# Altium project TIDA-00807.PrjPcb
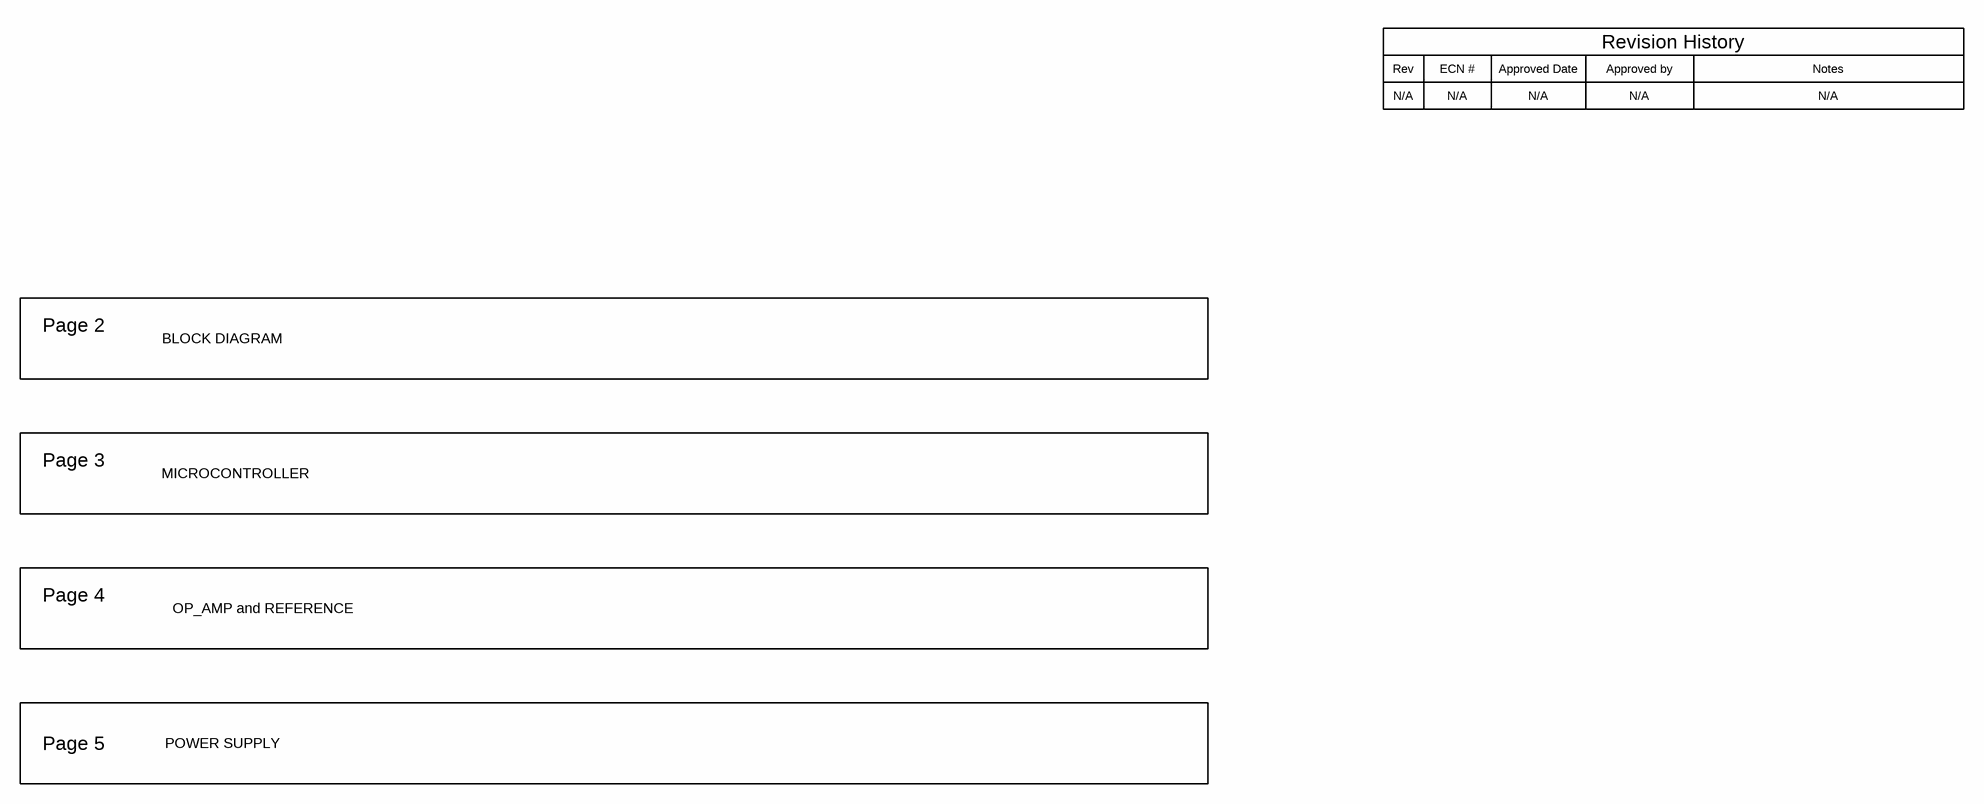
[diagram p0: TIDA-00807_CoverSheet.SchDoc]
CopyrightYear: 2016; PCB_Layout: Manjunath M; PCB_Rev: E2; PRJ_Customer: Public Release; PRJ_Engineer: Srinivasa; PRJ_Number: TIDA-00807; PRJ_Title: TIDA-00807; SCH_Rev: E2; TechSupport: http://www.ti.com/support; TID: N/A
6 sheets, 166 parts. Net scope: flat (ports and power ports of the same name join across sheets).
Board file: TIDA-00807_E2.PcbDoc
Sheets:
  TIDA-00807_CoverSheet.SchDoc
  TIDA-00807_BLOCKDIAGRAM.SchDoc
  TIDA-00807_MICROCONTROLLER.SchDoc
  TIDA-00807_OP_AMP and REFERENCE.SchDoc
  TIDA-00807_POWER SUPPLY.SchDoc
  TIDA-00807_EVM_Hardware.SchDoc

## Sheet TIDA-00807_CoverSheet.SchDoc: CoverSheet
size 431 x 279 mm; Date: Not shown in title block; ApprovedBy: Not shown in title block; CheckedBy: Not shown in title block; Author: Not shown in title block; CompanyName: Not shown in title block; DrawnBy: Srinivasa; Engineer: Srinivasa; Organization: Not shown in title block; Address1: Not shown in title block; Address2: Not shown in title block; Address3: Not shown in title block; Address4: Not shown in title block; DocumentNumber: 1; Revision: Use project parameter SCH_Rev; SheetNumber: 1; SheetTotal: 6; PageSetup: Record=PageOptions¦CenterHorizontal=True¦CenterVertical=True¦PrintScale=1.00¦XCorrection=1.00¦YCorrection=1.00¦PrintKind=0¦BorderSize=5000000¦LeftOffset=0¦BottomOffset=0¦Orientation=2¦PaperLength=1000¦PaperWidth=1000¦Scale=100¦PaperSource=15¦PrintQuality=600¦MediaType=1¦DitherType=10¦PaperKind=Letter¦PrintScaleMode=1

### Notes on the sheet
- Rev
- N/A
- ECN #
- Approved Date
- Approved by
- Revision History
- Notes
- Page 2
- BLOCK DIAGRAM
- Page 3
- MICROCONTROLLER
- Page 4
- OP_AMP and REFERENCE
- Page 5
- POWER SUPPLY

## Sheet TIDA-00807_BLOCKDIAGRAM.SchDoc: BLOCK DIAGRAM
size 431 x 279 mm; Date: Not shown in title block; ApprovedBy: Not shown in title block; CheckedBy: Not shown in title block; Author: Not shown in title block; CompanyName: Not shown in title block; DrawnBy: Srinivasa; Engineer: Srinivasa; Organization: Not shown in title block; Address1: Not shown in title block; Address2: Not shown in title block; Address3: Not shown in title block; Address4: Not shown in title block; DocumentNumber: 1; Revision: Use project parameter SCH_Rev; SheetNumber: 2; SheetTotal: 6; PageSetup: Record=PageOptions¦CenterHorizontal=True¦CenterVertical=True¦PrintScale=1.00¦XCorrection=1.00¦YCorrection=1.00¦PrintKind=0¦BorderSize=5000000¦LeftOffset=0¦BottomOffset=0¦Orientation=2¦PaperLength=1000¦PaperWidth=1000¦Scale=100¦PaperSource=15¦PrintQuality=600¦MediaType=1¦DitherType=10¦PaperKind=Letter¦PrintScaleMode=1
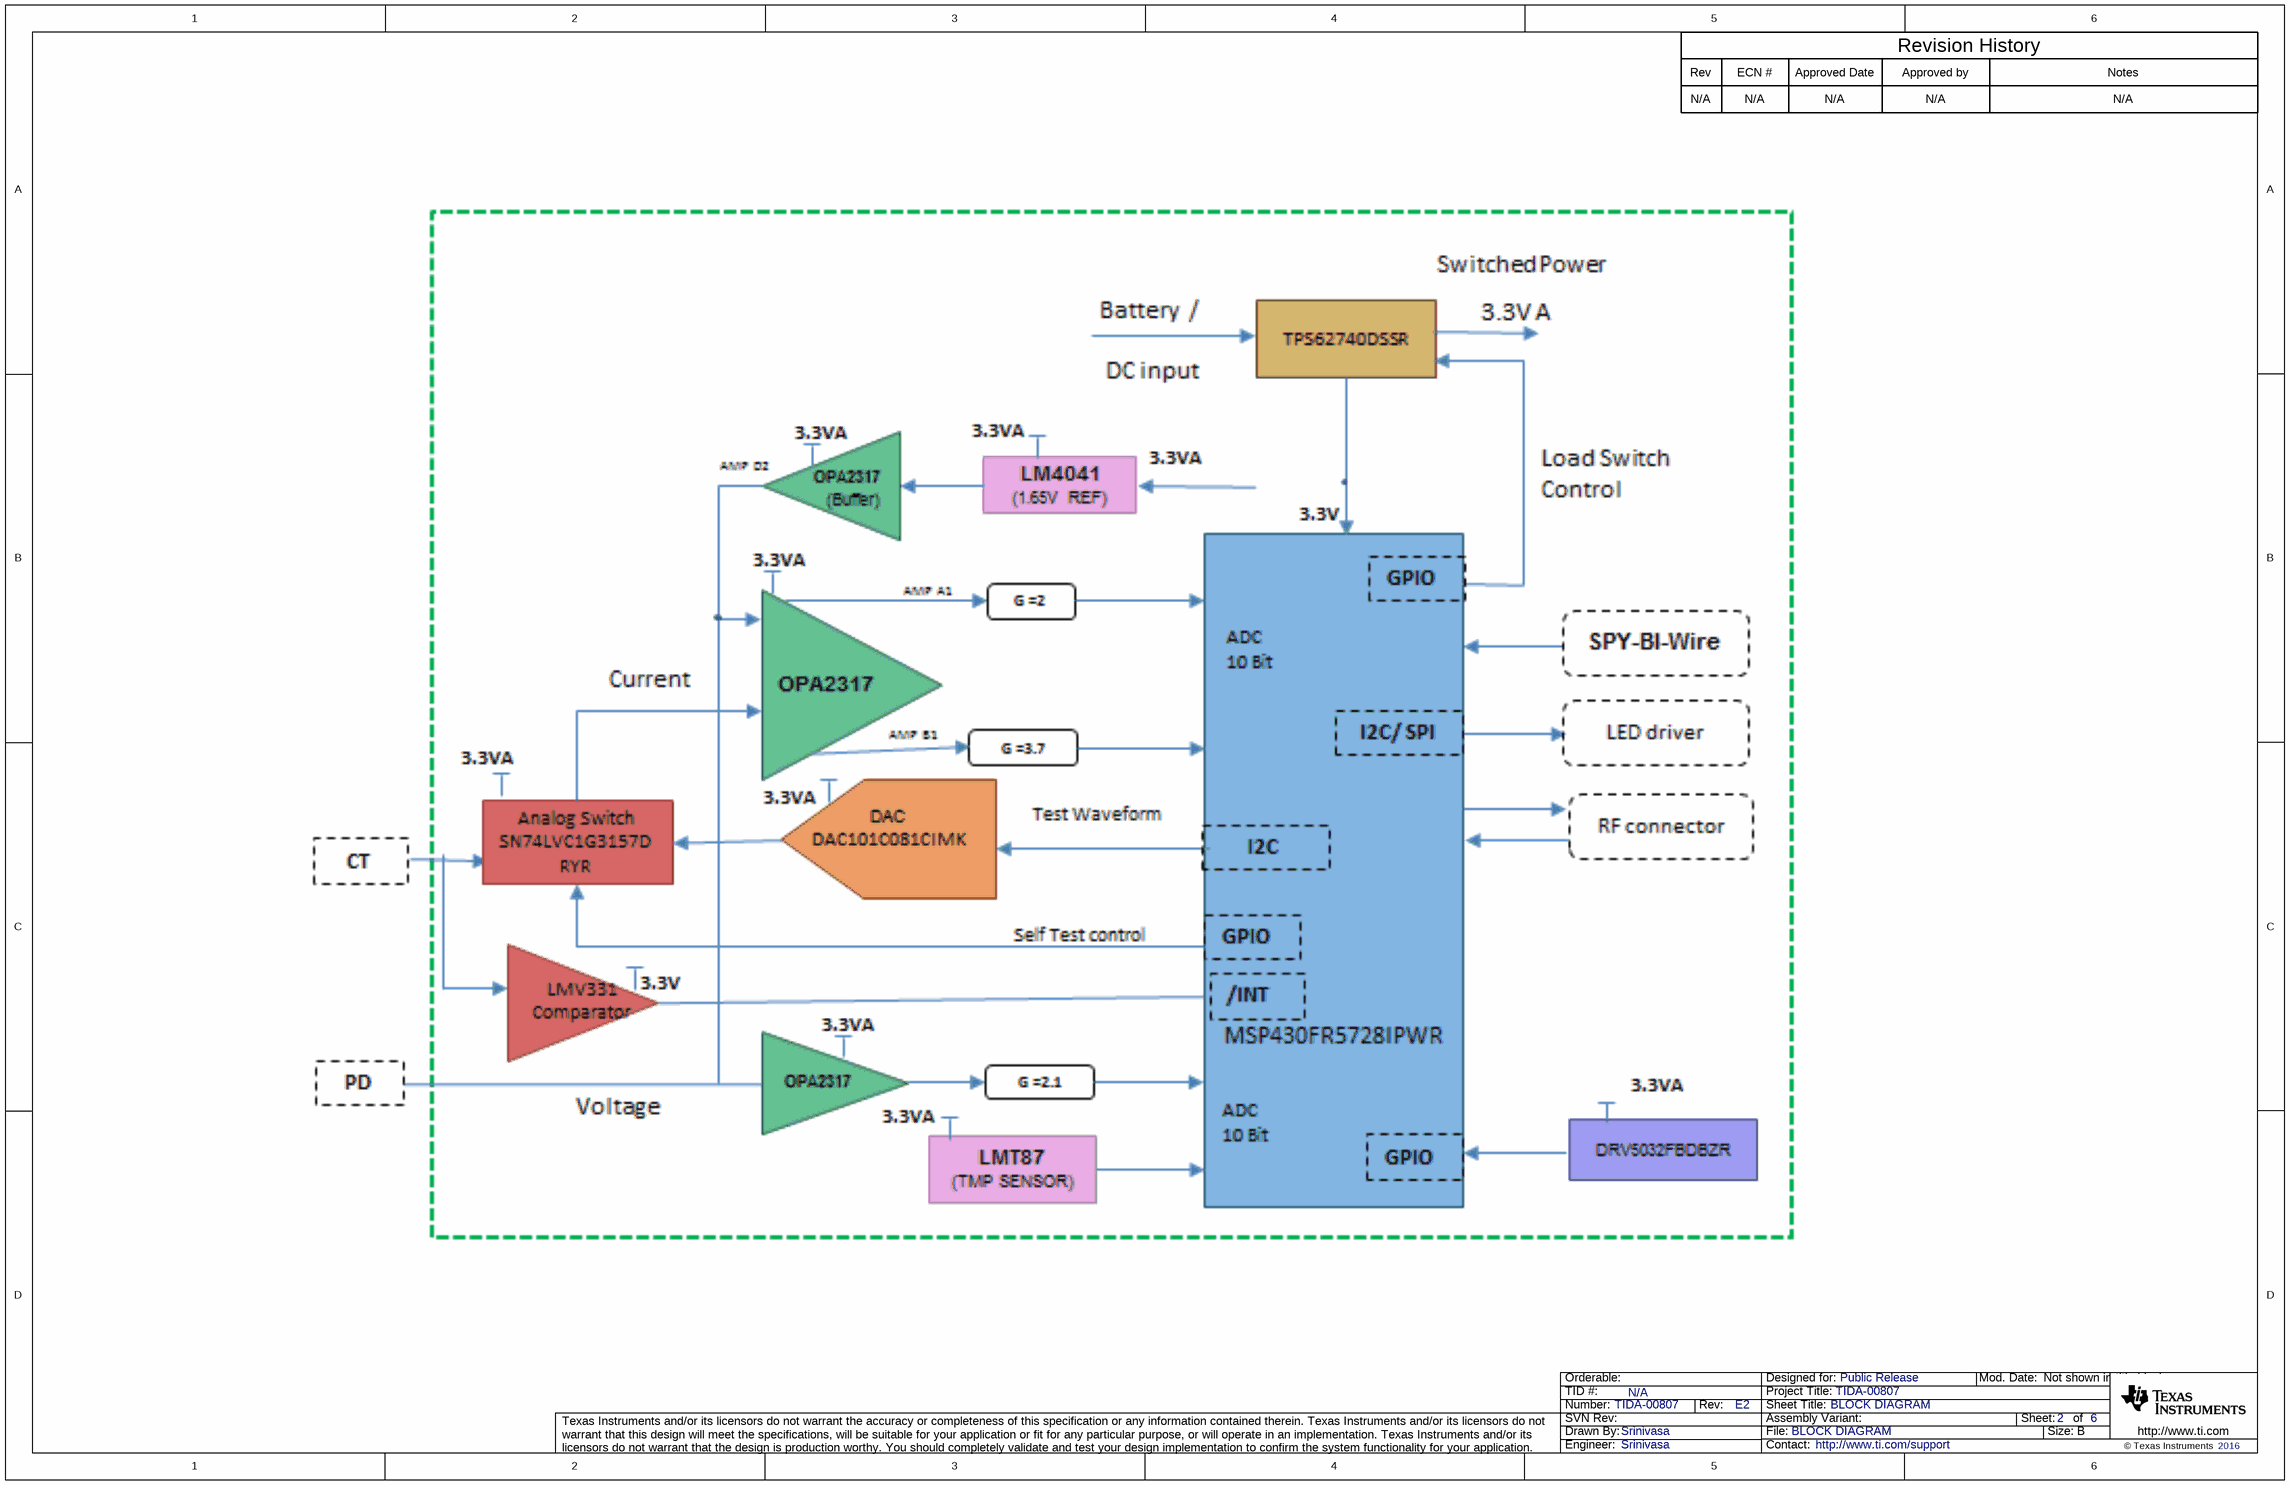
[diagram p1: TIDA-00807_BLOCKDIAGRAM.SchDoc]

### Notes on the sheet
- Rev
- N/A
- ECN #
- Approved Date
- Approved by
- Revision History
- Notes

## Sheet TIDA-00807_MICROCONTROLLER.SchDoc: MICROCONTROLLER
size 431 x 279 mm; Date: Not shown in title block; ApprovedBy: Not shown in title block; CheckedBy: Not shown in title block; Author: Not shown in title block; CompanyName: Not shown in title block; DrawnBy: Srinivasa; Engineer: Srinivasa; Organization: Not shown in title block; Address1: Not shown in title block; Address2: Not shown in title block; Address3: Not shown in title block; Address4: Not shown in title block; DocumentNumber: 1; Revision: Use project parameter SCH_Rev; SheetNumber: 3; SheetTotal: 6; PageSetup: Record=PageOptions¦CenterHorizontal=True¦CenterVertical=True¦PrintScale=1.00¦XCorrection=1.00¦YCorrection=1.00¦PrintKind=0¦BorderSize=5000000¦LeftOffset=0¦BottomOffset=0¦Orientation=2¦PaperLength=1000¦PaperWidth=1000¦Scale=100¦PaperSource=15¦PrintQuality=600¦MediaType=1¦DitherType=10¦PaperKind=Letter¦PrintScaleMode=1
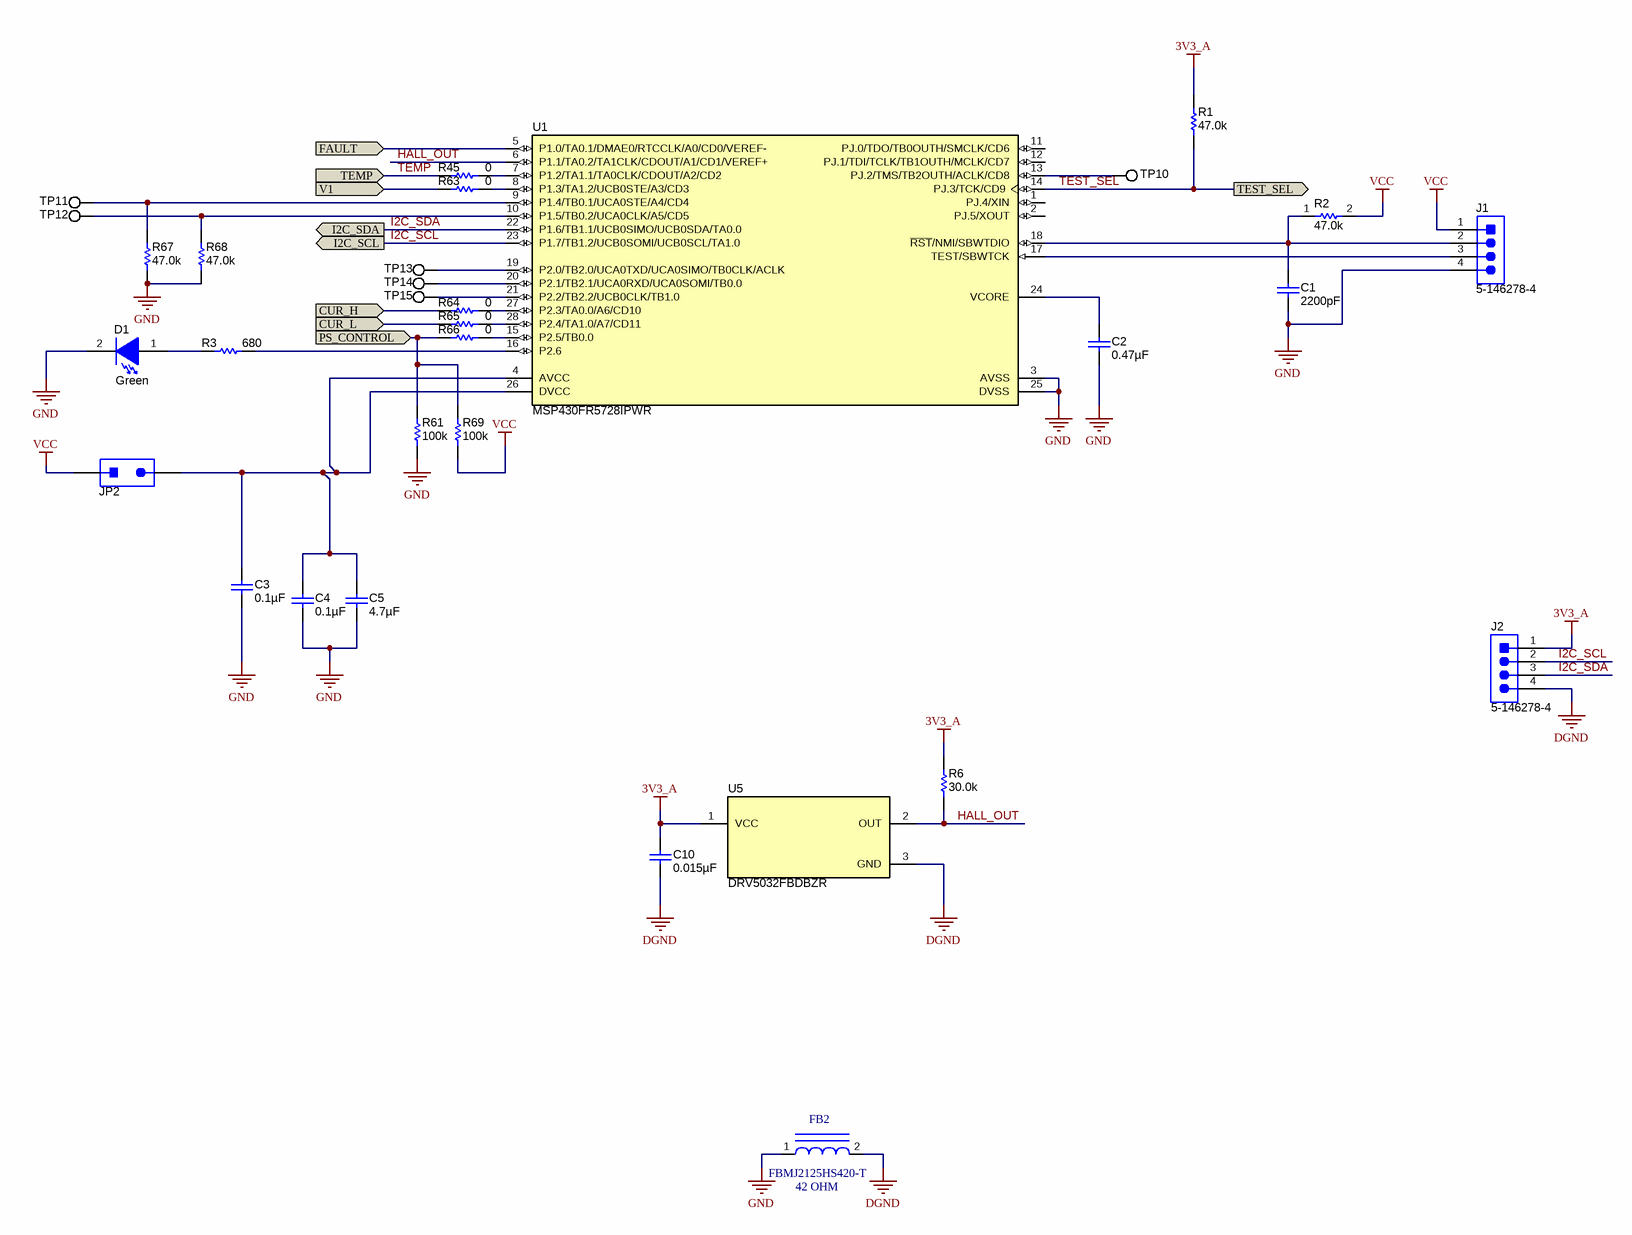
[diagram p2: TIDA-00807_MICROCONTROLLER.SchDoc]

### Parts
C1  ValueDisplayed: 2200pF  [0603]  (hidden comment: GRM188R71C222KA01D)
C2  ValueDisplayed: 0.47µF  [0603]  (hidden comment: C0603C474K9RACTU)
C3  ValueDisplayed: 0.1µF  [0603]
C4  ValueDisplayed: 0.1µF  [0603]
C5  ValueDisplayed: 4.7µF  [0603]  (hidden comment: GRM188R60J475ME19D)
C10  ValueDisplayed: 0.015µF  [0603]  (hidden comment: GRM188R71E153KA01D)
D1  value Green  [LG L29K_GREEN]  (hidden comment: LG L29K-G2J1-24-Z)
FB2  FBMJ2125HS420-T  value 42 OHM  [0805_hv]
J1  5-146278-4  [TE_5-146278-4]
J2  5-146278-4  [TE_5-146278-4]
JP2  5-146280-2  [TSW-102-07-G-S]  (value not drawn)
R1  ValueDisplayed: 47.0k  [0603]  (hidden comment: RC0603FR-0747KL)
R2  ValueDisplayed: 47.0k  [0603]  (hidden comment: RC0603FR-0747KL)
R3  ValueDisplayed: 680  [0603]  (hidden comment: RC0603FR-07680RL)
R6  ValueDisplayed: 30.0k  [0603]  (hidden comment: RC0603FR-0730KL)
R45  ValueDisplayed: 0  [0603]  (hidden comment: ERJ-3GEY0R00V)
R61  value 100k  [0603]  (hidden comment: CRCW0603100KFKEA)
R63  ValueDisplayed: 0  [0603]  (hidden comment: ERJ-3GEY0R00V)
R64  ValueDisplayed: 0  [0603]  (hidden comment: ERJ-3GEY0R00V)
R65  ValueDisplayed: 0  [0603]  (hidden comment: ERJ-3GEY0R00V)
R66  ValueDisplayed: 0  [0603]  (hidden comment: ERJ-3GEY0R00V)
R67  ValueDisplayed: 47.0k  [0603]  (hidden comment: RC0603FR-0747KL)
R68  ValueDisplayed: 47.0k  [0603]  (hidden comment: RC0603FR-0747KL)
R69  value 100k  [0603]  (hidden comment: CRCW0603100KFKEA)
TP10  TP105-01-09  [CC_TP105-01-09]  (value not drawn)
TP11  TP105-01-09  [CC_TP105-01-09]  (value not drawn)
TP12  TP105-01-09  [CC_TP105-01-09]  (value not drawn)
TP13  TP105-01-09  [CC_TP105-01-09]  (value not drawn)
TP14  TP105-01-09  [CC_TP105-01-09]  (value not drawn)
TP15  TP105-01-09  [CC_TP105-01-09]  (value not drawn)
U1  MSP430FR5728IPWR  [PW0028A_N]
U5  DRV5032FBDBZR  [DBZ0003A_N]

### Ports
CUR_H (in), CUR_L (in), FAULT (in), I2C_SCL (out), I2C_SDA (out), PS_CONTROL (in), TEMP (in), TEST_SEL (out), V1 (in)

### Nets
3V3_A: C10.1 J2.1 R1.2 R6.2 U5.1(VCC)
DGND: C10.2 FB2.2 J2.4 U5.3(GND)
GND: C1.2 C2.2 C3.2 C4.2 C5.2 D1.2(K) FB2.1 J1.4 R61.2 R67.1 R68.1 U1.3(AVSS) U1.25(DVSS)
VCC: J1.1 JP2.1 R2.2 R69.2
CUR_H: R64.2 ; port CUR_H
CUR_L: R65.2 ; port CUR_L
FAULT: U1.5(P1.0/TA0.1/DMAE0/RTCCLK/A0/CD0/VEREF-) ; port FAULT
HALL_OUT: R6.1 U1.6(P1.1/TA0.2/TA1CLK/CDOUT/A1/CD1/VEREF+) U5.2(OUT)
I2C_SCL: J2.2 U1.23(P1.7/TB1.2/UCB0SOMI/UCB0SCL/TA1.0) ; port I2C_SCL
I2C_SDA: J2.3 U1.22(P1.6/TB1.1/UCB0SIMO/UCB0SDA/TA0.0) ; port I2C_SDA
PS_CONTROL: R61.1 R66.2 R69.1 ; port PS_CONTROL
TEMP: R45.2 ; port TEMP
TEST_SEL: R1.1 U1.14(PJ.3/TCK/CD9) ; port TEST_SEL
V1: R63.2 ; port V1
NetC1_1: C1.1 J1.2 R2.1 U1.18(~{RST}/NMI/SBWTDIO)
NetC2_1: C2.1 U1.24(VCORE)
NetC3_1: C3.1 C4.1 C5.1 JP2.2 U1.4(AVCC) U1.26(DVCC)
NetD1_1: D1.1(A) R3.2
NetJ1_3: J1.3 U1.17(TEST/SBWTCK)
NetR3_1: R3.1 U1.16(P2.6)
NetR45_1: R45.1 U1.7(P1.2/TA1.1/TA0CLK/CDOUT/A2/CD2)
NetR63_1: R63.1 U1.8(P1.3/TA1.2/UCB0STE/A3/CD3)
NetR64_1: R64.1 U1.27(P2.3/TA0.0/A6/CD10)
NetR65_1: R65.1 U1.28(P2.4/TA1.0/A7/CD11)
NetR66_1: R66.1 U1.15(P2.5/TB0.0)
NetR67_2: R67.2 TP11.1 U1.9(P1.4/TB0.1/UCA0STE/A4/CD4)
NetR68_2: R68.2 TP12.1 U1.10(P1.5/TB0.2/UCA0CLK/A5/CD5)
NetTP10_1: TP10.1 U1.13(PJ.2/TMS/TB2OUTH/ACLK/CD8)
NetTP13_1: TP13.1 U1.19(P2.0/TB2.0/UCA0TXD/UCA0SIMO/TB0CLK/ACLK)
NetTP14_1: TP14.1 U1.20(P2.1/TB2.1/UCA0RXD/UCA0SOMI/TB0.0)
NetTP15_1: TP15.1 U1.21(P2.2/TB2.2/UCB0CLK/TB1.0)

Not connected (* = marked no-connect by the designer): U1 1(PJ.4/XIN) 2(PJ.5/XOUT) 11(PJ.0/TDO/TB0OUTH/SMCLK/CD6) 12(PJ.1/TDI/TCLK/TB1OUTH/MCLK/CD7)

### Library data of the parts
C1 = GRM188R71C222KA01D: CAP, CERM, 2200 pF, 16 V, +/- 10%, X7R, 0603; Manufacturer: MuRata; Polarized: N; CompType: Capacitor; Value: 2200pF; U/M: EA; Cap_F: 0.0000000022; Tolerance_%: 10; Value1: Unknown; VDC_V: 16; Value2: 16V; TaMin_C: -55; TaMax_C: 125; AEC Category: Q200
C2 = C0603C474K9RACTU: CAP, CERM, 0.47 µF, 6.3 V, +/- 10%, X7R, 0603; Manufacturer: Kemet; Polarized: N; CompType: Capacitor; Value: 0.47uF; U/M: EA; Cap_F: 0.00000047; Tolerance_%: 10; Value1: Unknown; VDC_V: 6.3; Value2: 6.3V; TaMin_C: -55; TaMax_C: 125; AEC Category: Q200
C3 C4 = 06033C104JAT2A: CAP, CERM, 0.1uF, 25V, +/-5%, X7R, 0603; Manufacturer: AVX; Polarized: N; CompType: Capacitor; U/M: EA; Cap_F: 0.0000001; Tolerance_%: 5; ESR_Ohm: 0.05; Value1: 0.05 ohm; VDC_V: 25; TaMin_C: -55; TaMax_C: 125
C5 = GRM188R60J475ME19D: CAP, CERM, 4.7 µF, 6.3 V, +/- 20%, X5R, 0603; Manufacturer: MuRata; Polarized: N; CompType: Capacitor; Value: 4.7uF; U/M: EA; Cap_F: 0.0000047; Tolerance_%: 20; ESR_ohm: 0.001; Value1: 0.001 ohm; VDC_V: 6.3; Value2: 6.3V; TaMin_C: -55; TaMax_C: 85; AEC Category: Q200
C10 = GRM188R71E153KA01D: CAP, CERM, 0.015 µF, 25 V, +/- 10%, X7R, 0603; Manufacturer: MuRata; Polarized: N; CompType: Capacitor; Value: 0.015uF; U/M: EA; Cap_F: 0.000000015; Tolerance_%: 10; Value1: Unknown; VDC_V: 25; Value2: 25V; TaMin_C: -55; TaMax_C: 125; AEC Category: Q200
D1 = LG L29K-G2J1-24-Z: LED, Green, SMD; Manufacturer: OSRAM; Vf_V: 1.7; Value2: 1.7V; Io_A: 0.002; Tjmax_C: 110; Value1: W; U/M: EA
FB2 = FBMJ2125HS420-T: FERRITE BEAD, 42 OHM, 4 A, DCR0.008 OHM, SMT-0805; Manufacturer: TAIYO YUDEN; SymbolCreator: x0199378
J1 J2 = 5-146278-4: Header, 100mil, 4x1, Tin, TH; Manufacturer: TE Connectivity; SymbolCreator: a0412235
JP2 = TSW-102-07-G-S: Header, 100mil, 2x1, Gold, TH; Manufacturer: TE Connectivity; SymbolCreator: a0412235; U/M: EA
R1 R2 R67 R68 = RC0603FR-0747KL: RES, 47.0 k, 1%, 0.1 W, 0603; Manufacturer: Yageo America; CompType: Resistor; Value: 47.0k; Res_ohm: 47000; Value_Code: 47k0; Tolerance_%: 1; Power_W: 0.1; Value2: 0.1W; VDC_V: 150; TempCo: 200 ppm/C; U/M: EA; AEC Category: Q200
R3 = RC0603FR-07680RL: RES, 680, 1%, 0.1 W, 0603; Manufacturer: Yageo America; CompType: Resistor; Value: 680; Value_Code: 680R; Tolerance_%: 1; Power_W: 0.1; Value2: 0.1W; VDC_V: 150; TempCo: 200 ppm/C; U/M: EA; AEC Category: Q200
R6 = RC0603FR-0730KL: RES, 30.0 k, 1%, 0.1 W, 0603; Manufacturer: Yageo America; CompType: Resistor; Value: 30.0k; Res_ohm: 30000; Value_Code: 30k0; Tolerance_%: 1; Power_W: 0.1; Value2: 0.1W; VDC_V: 150; TempCo: 200 ppm/C; U/M: EA; AEC Category: Q200
R45 R63-R66 = ERJ-3GEY0R00V: RES, 0, 5%, 0.1 W, 0603; Manufacturer: Panasonic; CompType: Resistor; Value: 0; Value_Code: 0000; Tolerance_%: 5; Power_W: 0.1; Value2: 0.1W; VDC_V: 50; TempCo: 600 ppm/C; EIA_Code: E24; U/M: EA; AEC Category: Q200
R61 R69 = CRCW0603100KFKEA: RES, 100k ohm, 1%, 0.1W, 0603; Manufacturer: Vishay-Dale; CompType: Resistor; Res_ohm: 100000; Tolerance_%: 1; Power_W: 0.1; VDC_V: 75; TempCo: 100 ppm/C; EIA_Code: E96; U/M: EA
TP10-TP15 = TP105-01-09: Test Point, Miniature, White, TH; Manufacturer: Components Corporation; SymbolCreator: Altium
U1 = MSP430FR5728IPWR: MIXED SIGNAL MICROCONTROLLER, PW0028A; Manufacturer: Texas Instruments; ADC: 10-bit SAR; ADC Channels: 10; Brown Out Reset: Yes; DMA: 3; Eco-Plan: Green (RoHS & no Sb/Br); FRAM(KB): 16; Frequency(MHz): 8; GPIO: 17; Multiplier: 32x32; SRAM(B): 1024; SubFamily: FRAM Series; USCI_A (UART/LIN/IrDA/SPI): 1; SymbolCreator: Altium/a0412235; CompType: IC; U/M: EA
U5 = DRV5032FBDBZR: Ultra-Low Power Digital-Switch Hall Effect Sensor, DBZ0003A; Manufacturer: Texas Instruments; SymbolCreator: Altium; CompType: IC; U/M: EA

## Sheet TIDA-00807_OP_AMP and REFERENCE.SchDoc: OP-AMP and REFERENCE
size 431 x 279 mm; Date: Not shown in title block; ApprovedBy: Not shown in title block; CheckedBy: Not shown in title block; Author: Not shown in title block; CompanyName: Not shown in title block; DrawnBy: Srinivasa; Engineer: Srinivasa; Organization: Not shown in title block; Address1: Not shown in title block; Address2: Not shown in title block; Address3: Not shown in title block; Address4: Not shown in title block; DocumentNumber: 1; Revision: Use project parameter SCH_Rev; SheetNumber: 4; SheetTotal: 6; PageSetup: Record=PageOptions|CenterHorizontal=True|CenterVertical=True|PrintScale=1.00|XCorrection=1.00|YCorrection=1.00|PrintKind=0|BorderSize=5000000|LeftOffset=0|BottomOffset=0|Orientation=2|PaperLength=1000|PaperWidth=1000|Scale=100|PaperSource=15|PrintQuality=600|MediaType=1|DitherType=10|PaperKind=Letter|PrintScaleMode=1
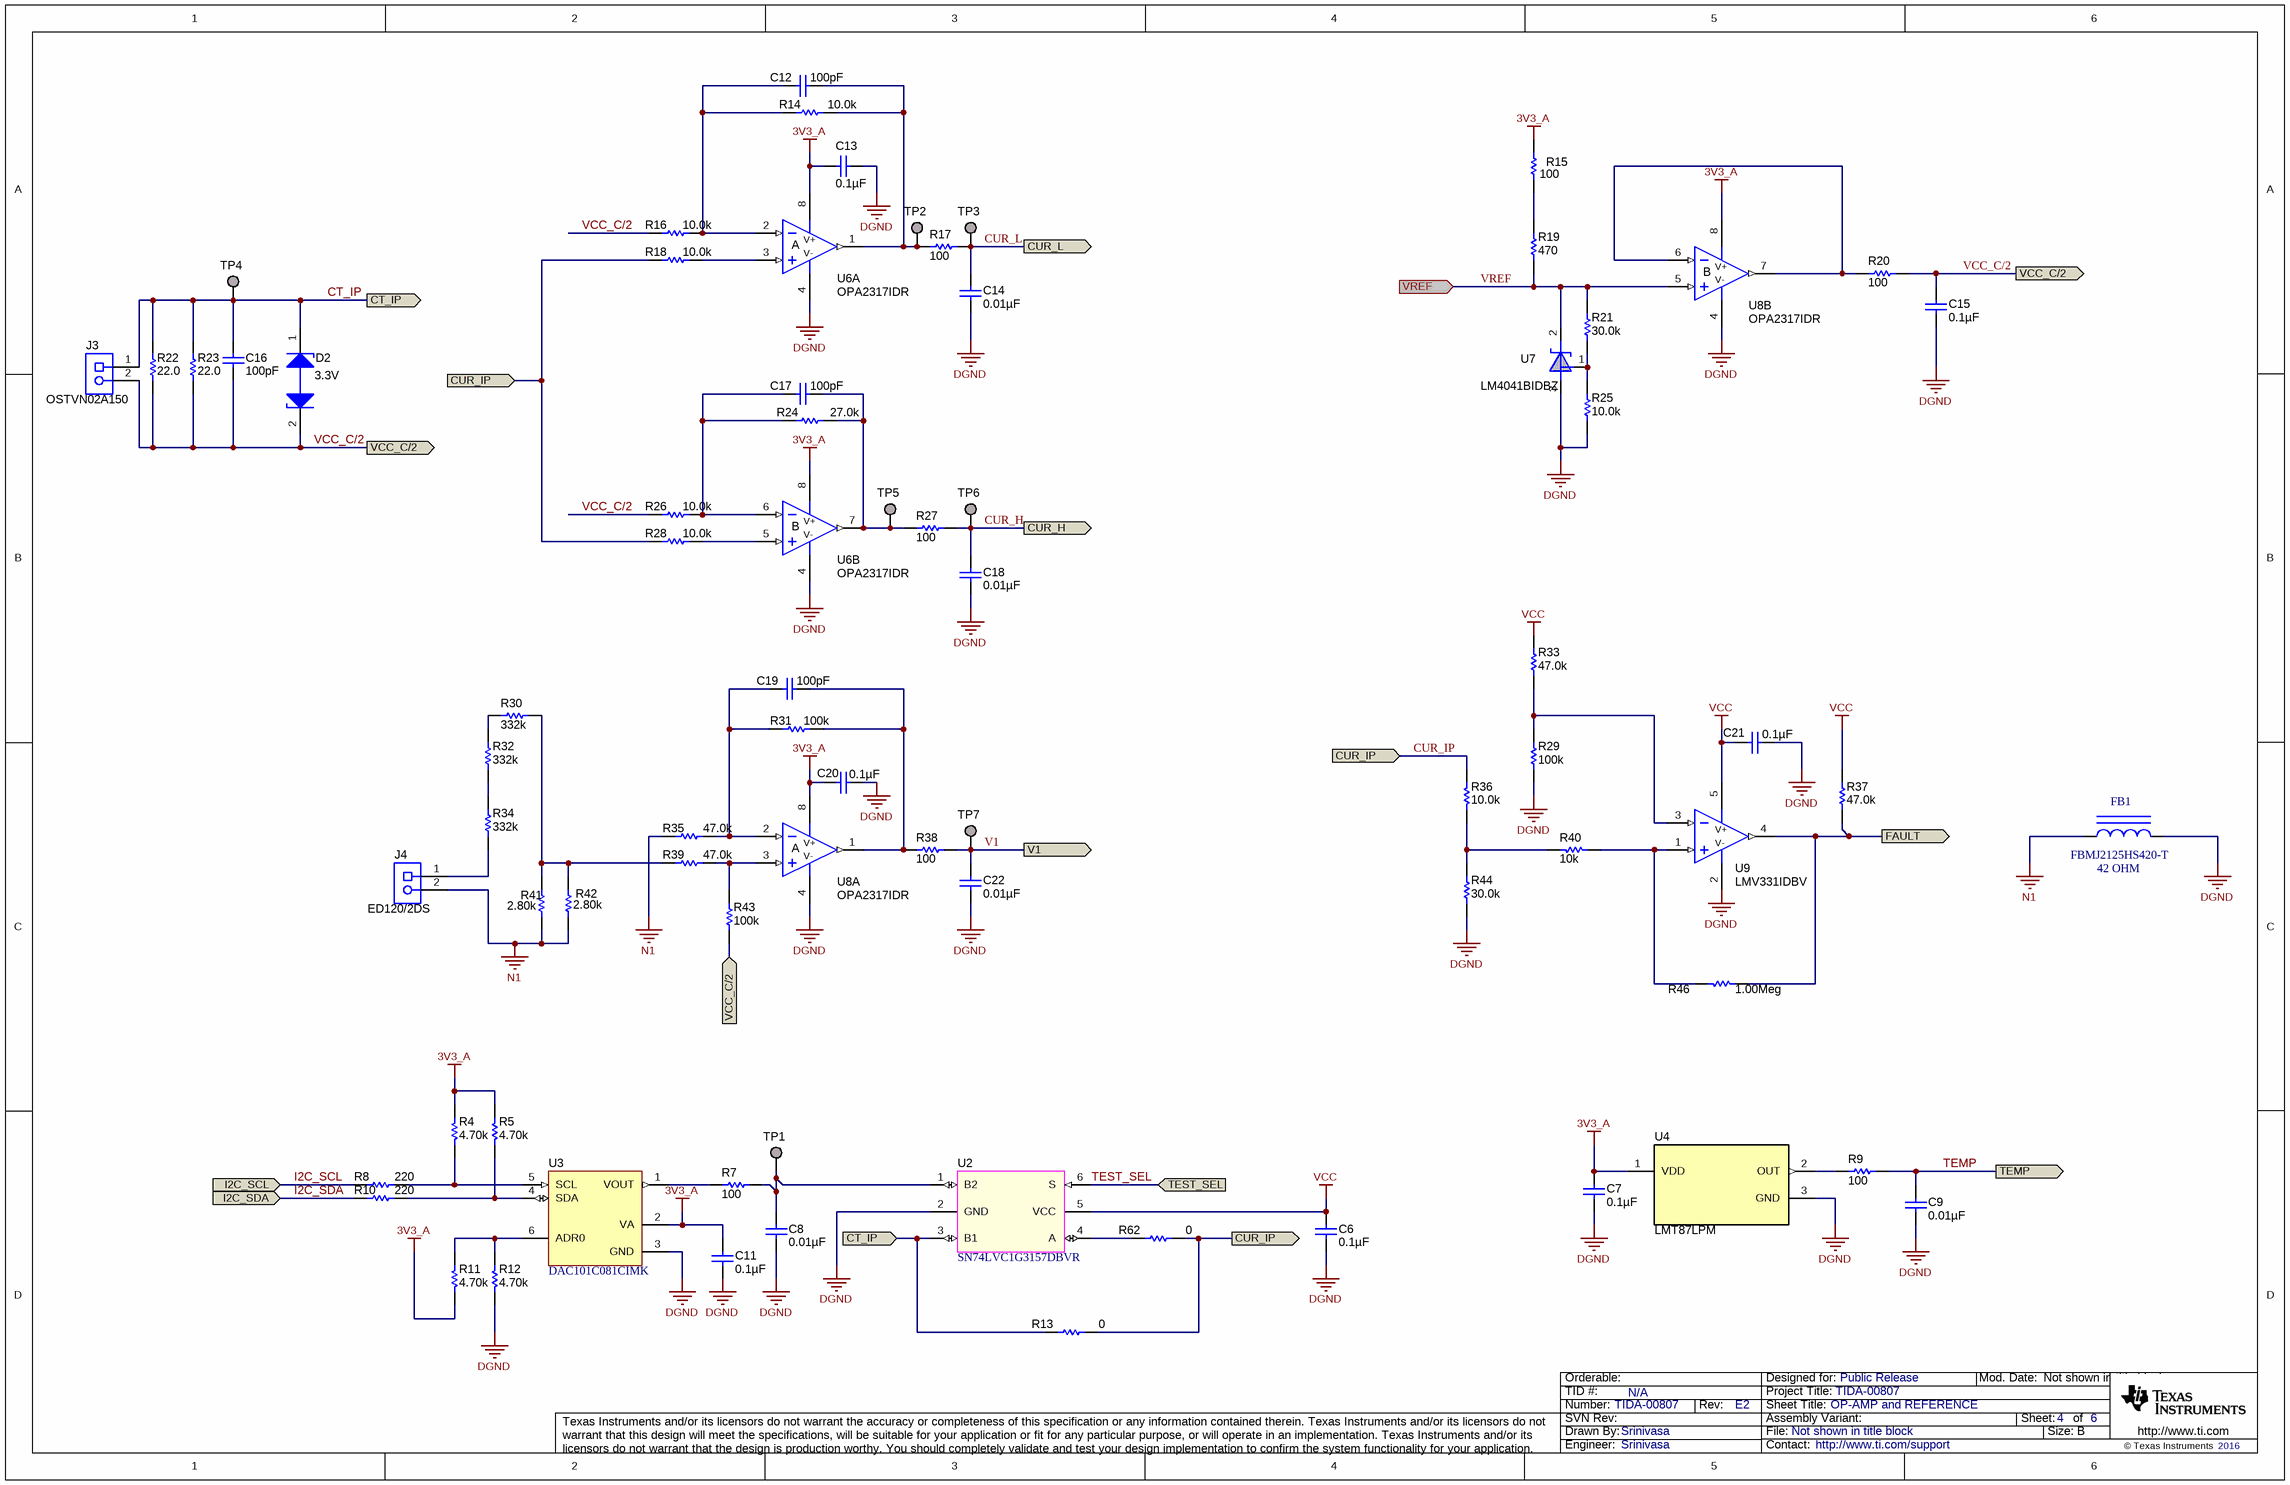
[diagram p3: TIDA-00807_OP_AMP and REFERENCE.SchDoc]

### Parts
C6  ValueDisplayed: 0.1µF  [0603]
C7  ValueDisplayed: 0.1µF  [0603]
C8  ValueDisplayed: 0.01µF  [0603]  (hidden comment: C1608C0G1E103J)
C9  ValueDisplayed: 0.01µF  [0603]  (hidden comment: C1608C0G1E103J)
C11  ValueDisplayed: 0.1µF  [0603]
C12  ValueDisplayed: 100pF  [0603]  (hidden comment: 06033C101KAT2A)
C13  ValueDisplayed: 0.1µF  [0603]
C14  ValueDisplayed: 0.01µF  [0603]  (hidden comment: C1608C0G1E103J)
C15  ValueDisplayed: 0.1µF  [0603]  (hidden comment: 06033C104JAT2A)
C16  ValueDisplayed: 100pF  [0603]  (hidden comment: 06033C101KAT2A)
C17  ValueDisplayed: 100pF  [0603]  (hidden comment: 06033C101KAT2A)
C18  ValueDisplayed: 0.01µF  [0603]  (hidden comment: C1608C0G1E103J)
C19  ValueDisplayed: 100pF  [0603]  (hidden comment: 06033C101KAT2A)
C20  ValueDisplayed: 0.1µF  [0603]  (hidden comment: 06033C104JAT2A)
C21  ValueDisplayed: 0.1µF  [0603]  (hidden comment: 06033C104JAT2A)
C22  ValueDisplayed: 0.01µF  [0603]  (hidden comment: C1608C0G1E103J)
D2  value 3.3V  [DIO_SOD323]  (hidden comment: PESD3V3L1BA)
FB1  FBMJ2125HS420-T  value 42 OHM  [0805_hv]
J3  OSTVN02A150  [On-Shore_OSTVN02A150]
J4  ED120/2DS  [CONN_ED120-2DS]
R4  ValueDisplayed: 4.70k  [0603]  (hidden comment: RC0603FR-074K7L)
R5  ValueDisplayed: 4.70k  [0603]  (hidden comment: RC0603FR-074K7L)
R7  value 100  [0603]  (hidden comment: CRCW0603100RFKEA)
R8  ValueDisplayed: 220  [0603]  (hidden comment: RC0603FR-07220RL)
R9  value 100  [0603]  (hidden comment: CRCW0603100RFKEA)
R10  ValueDisplayed: 220  [0603]  (hidden comment: RC0603FR-07220RL)
R11  ValueDisplayed: 4.70k  [0603]  (hidden comment: RC0603FR-074K7L)
R12  ValueDisplayed: 4.70k  [0603]  (hidden comment: RC0603FR-074K7L)
R13  ValueDisplayed: 0  [0603]  (hidden comment: ERJ-3GEY0R00V)
R14  value 10.0k  [0603]  (hidden comment: CRCW060310K0FKEA)
R15  value 100  [0603]  (hidden comment: CRCW0603100RFKEA)
R16  value 10.0k  [0603]  (hidden comment: CRCW060310K0FKEA)
R17  value 100  [0603]  (hidden comment: CRCW0603100RFKEA)
R18  value 10.0k  [0603]  (hidden comment: CRCW060310K0FKEA)
R19  value 470  [0603]  (hidden comment: RC0603FR-07470RL)
R20  value 100  [0603]  (hidden comment: CRCW0603100RFKEA)
R21  value 30.0k  [0603]  (hidden comment: RC0603FR-0730KL)
R22  value 22.0  [1206]  (hidden comment: RC1206FR-0722RL)
R23  value 22.0  [1206]  (hidden comment: RC1206FR-0722RL)
R24  value 27.0k  [0603]  (hidden comment: RC0603FR-0727KL)
R25  value 10.0k  [0603]  (hidden comment: CRCW060310K0FKEA)
R26  value 10.0k  [0603]  (hidden comment: CRCW060310K0FKEA)
R27  value 100  [0603]  (hidden comment: CRCW0603100RFKEA)
R28  value 10.0k  [0603]  (hidden comment: CRCW060310K0FKEA)
R29  value 100k  [0603]  (hidden comment: CRCW0603100KFKEA)
R30  value 332k  [1206]  (hidden comment: ERJ-8ENF3323V)
R31  value 100k  [0603]  (hidden comment: CRCW0603100KFKEA)
R32  value 332k  [1206]  (hidden comment: ERJ-8ENF3323V)
R33  ValueDisplayed: 47.0k  [0603]  (hidden comment: RC0603FR-0747KL)
R34  value 332k  [1206]  (hidden comment: ERJ-8ENF3323V)
R35  ValueDisplayed: 47.0k  [0603]  (hidden comment: RC0603FR-0747KL)
R36  value 10.0k  [0603]  (hidden comment: CRCW060310K0FKEA)
R37  ValueDisplayed: 47.0k  [0603]  (hidden comment: RC0603FR-0747KL)
R38  value 100  [0603]  (hidden comment: CRCW0603100RFKEA)
R39  ValueDisplayed: 47.0k  [0603]  (hidden comment: RC0603FR-0747KL)
R40  value 10k  [0603]  (hidden comment: CRCW060310K0FKEA)
R41  value 2.80k  [1206]  (hidden comment: CRCW12062K80FKEA)
R42  value 2.80k  [1206]  (hidden comment: CRCW12062K80FKEA)
R43  value 100k  [0603]  (hidden comment: CRCW0603100KFKEA)
R44  ValueDisplayed: 30.0k  [0603]  (hidden comment: RC0603FR-0730KL)
R46  value 1.00Meg  [0603]  (hidden comment: CRCW06031M00FKEA)
R62  ValueDisplayed: 0  [0603]  (hidden comment: ERJ-3GEY0R00V)
TP1  TESTPOINT  [TP_H045P075]  (value not drawn)  (no BOM)
TP2  TESTPOINT  [TP_H045P075]  (value not drawn)  (no BOM)
TP3  TESTPOINT  [TP_H045P075]  (value not drawn)  (no BOM)
TP4  TESTPOINT  [TP_H045P075]  (value not drawn)  (no BOM)
TP5  TESTPOINT  [TP_H045P075]  (value not drawn)  (no BOM)
TP6  TESTPOINT  [TP_H045P075]  (value not drawn)  (no BOM)
TP7  TESTPOINT  [TP_H045P075]  (value not drawn)  (no BOM)
U2  SN74LVC1G3157DBVR  [SOT23-6]
U3  DAC101C081CIMK  [MK06A_N]
U4  LMT87LPM  [LP0003A]
U6  OPA2317IDR  [D0008A_N]  (parts A,B of 2)
U7  LM4041BIDBZ  [SOT-23]
U8  OPA2317IDR  [D0008A_N]  (parts A,B of 2)
U9  LMV331IDBV  [DBV0005A_N]

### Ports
CT_IP (in), CT_IP (out), CUR_H (out), CUR_IP (in), CUR_IP (out), CUR_L (out), FAULT (out), I2C_SCL (in), I2C_SDA (in), TEMP (out), TEST_SEL (in), V1 (out), VCC_C/2 (in), VCC_C/2 (out), VREF (in)

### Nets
3V3_A: C7.1 C11.1 C13.1 C20.2 R4.2 R5.2 R11.1 R15.1 U3.2(VA) U4.1(VDD) U6.8(V+) U8.8(V+)
DGND: C6.2 C7.2 C8.1 C9.1 C11.2 C13.2 C14.1 C15.1 C18.1 C20.1 C21.1 C22.1 FB1.2 R12.1 R25.1 R29.1 R44.1 U2.2(GND) U3.3(GND) U4.3(GND) U6.4(V-) U7.3(A) U8.4(V-) U9.2(V-)
N1: FB1.1 J4.2 R35.2 R41.2 R42.2
VCC: C6.1 C21.2 R33.2 R37.2 U2.5(VCC) U9.5(V+)
CT_IP: C16.1 D2.1(K) J3.1 R13.1 R22.2 R23.2 TP4.1 U2.3(B1) ; port CT_IP
CUR_H: C18.2 R27.2 TP6.1 ; port CUR_H
CUR_IP: R13.2 R18.1 R28.1 R36.2 R62.1 ; port CUR_IP
CUR_L: C14.2 R17.2 TP3.1 ; port CUR_L
FAULT: R37.1 R46.2 U9.4(OUT) ; port FAULT
I2C_SCL: R8.1 ; port I2C_SCL
I2C_SDA: R10.1 ; port I2C_SDA
TEMP: C9.2 R9.2 ; port TEMP
TEST_SEL: U2.6(S) ; port TEST_SEL
V1: C22.2 R38.2 TP7.1 ; port V1
VCC_C/2: C15.2 C16.2 D2.2(K) J3.2 R16.1 R20.2 R22.1 R23.1 R26.1 R43.2 ; port VCC_C/2
VREF: R19.1 R21.2 U7.2(C) U8.5(IN+) ; port VREF
NetC8_2: C8.2 R7.2 TP1.1 U2.1(B2)
NetC12_1: C12.1 R14.1 R16.2 U6.2(IN-)
NetC12_2: C12.2 R14.2 R17.1 TP2.1 U6.1(OUT)
NetC17_1: C17.1 R24.1 R26.2 U6.6(IN-)
NetC17_2: C17.2 R24.2 R27.1 TP5.1 U6.7(OUT)
NetC19_1: C19.1 R31.2 R35.1 U8.2(IN-)
NetC19_2: C19.2 R31.1 R38.1 U8.1(OUT)
NetJ4_1: J4.1 R34.1
NetR4_1: R4.1 R8.2 U3.5(SCL)
NetR5_1: R5.1 R10.2 U3.4(SDA)
NetR7_1: R7.1 U3.1(VOUT)
NetR9_1: R9.1 U4.2(OUT)
NetR11_2: R11.2 R12.2 U3.6(ADR0)
NetR15_2: R15.2 R19.2
NetR18_2: R18.2 U6.3(IN+)
NetR20_1: R20.1 U8.6(IN-) U8.7(OUT)
NetR21_1: R21.1 R25.2 U7.1(FB)
NetR28_2: R28.2 U6.5(IN+)
NetR29_2: R29.2 R33.1 U9.3(IN-)
NetR30_1: R30.1 R39.2 R41.1 R42.1
NetR30_2: R30.2 R32.2
NetR32_1: R32.1 R34.2
NetR36_1: R36.1 R40.1 R44.2
NetR39_1: R39.1 R43.1 U8.3(IN+)
NetR40_2: R40.2 R46.1 U9.1(IN+)
NetR62_2: R62.2 U2.4(A)

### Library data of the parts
C6 C7 C11 C13 C15 C20 C21 = 06033C104JAT2A: as C3 on sheet TIDA-00807_MICROCONTROLLER
C8 C9 C14 C18 C22 = C1608C0G1E103J: CAP, CERM, 0.01uF, 25V, +/-5%, C0G/NP0, 0603; Manufacturer: TDK; Polarized: N; CompType: Capacitor; U/M: EA; Cap_F: 0.00000001; Tolerance_%: 5; Value1: Unknown; VDC_V: 25; TaMin_C: -55; TaMax_C: 125
C12 C16 C17 C19 = 06033C101KAT2A: CAP, CERM, 100pF, 25V, +/-10%, X7R, 0603; Manufacturer: AVX; Polarized: N; CompType: Capacitor; U/M: EA; Cap_F: 0.0000000001; Tolerance_%: 10; Value1: Unknown; VDC_V: 25; TaMin_C: -55; TaMax_C: 125
D2 = PESD3V3L1BA: DIODE, TVS, BIDIRECTIONAL, 3.3VWM, 26VC, SOD323; Manufacturer: NXP Semiconductor; SymbolCreator: x0199378
FB1 = FBMJ2125HS420-T: as FB2 on sheet TIDA-00807_MICROCONTROLLER
J3 = OSTVN02A150: Terminal Block, 2.54mm, 2x1, Brass, TH; Manufacturer: On-Shore Technology; SymbolCreator: a0412235
J4 = ED120/2DS: TERMINAL BLOCK 5.08MM VERT 2POS, TH; Manufacturer: On-Shore Technology; SymbolCreator: a0412235; U/M: EA
R4 R5 R11 R12 = RC0603FR-074K7L: RES, 4.70 k, 1%, 0.1 W, 0603; Manufacturer: Yageo America; CompType: Resistor; Value: 4.70k; Res_ohm: 4700; Value_Code: 4k70; Tolerance_%: 1; Power_W: 0.1; Value2: 0.1W; VDC_V: 150; TempCo: 200 ppm/C; U/M: EA; AEC Category: Q200
R7 R9 R15 R17 R20 R27 R38 = CRCW0603100RFKEA: RES, 100 ohm, 1%, 0.1W, 0603; Manufacturer: Vishay-Dale; CompType: Resistor; Value_Code: 100R; Tolerance_%: 1; Power_W: 0.1; VDC_V: 75; TempCo: 100 ppm/C; EIA_Code: E96; U/M: EA
R8 R10 = RC0603FR-07220RL: RES, 220, 1%, 0.1 W, 0603; Manufacturer: Yageo America; CompType: Resistor; Value: 220; Value_Code: 220R; Tolerance_%: 1; Power_W: 0.1; Value2: 0.1W; VDC_V: 150; TempCo: 200 ppm/C; U/M: EA; AEC Category: Q200
R13 R62 = ERJ-3GEY0R00V: as R45 on sheet TIDA-00807_MICROCONTROLLER
R14 R16 R18 R25 R26 R28 R36 = CRCW060310K0FKEA: RES, 10.0k ohm, 1%, 0.1W, 0603; Manufacturer: Vishay-Dale; CompType: Resistor; Res_ohm: 10000; Value_Code: 10k0; Tolerance_%: 1; Power_W: 0.1; VDC_V: 75; TempCo: 100 ppm/C; EIA_Code: E96; U/M: EA
R19 = RC0603FR-07470RL: RES, 470 ohm, 1%, 0.1W, 0603; Manufacturer: Yageo America; CompType: Resistor; Value_Code: 470R; Tolerance_%: 1; Power_W: 0.1; VDC_V: 150; TempCo: 200 ppm/C; U/M: EA
R21 = RC0603FR-0730KL: RES, 30.0k ohm, 1%, 0.1W, 0603; Manufacturer: Yageo America; CompType: Resistor; Res_ohm: 30000; Value_Code: 30k0; Tolerance_%: 1; Power_W: 0.1; VDC_V: 150; TempCo: 200 ppm/C; U/M: EA
R22 R23 = RC1206FR-0722RL: RES, 22.0 ohm, 1%, 0.25W, 1206; Manufacturer: Yageo America; CompType: Resistor; Res_ohm: 22; Value_Code: 22R0; Tolerance_%: 1; Power_W: 0.25; VDC_V: 200; TempCo: 100 ppm/C; U/M: EA
R24 = RC0603FR-0727KL: RES, 27.0k ohm, 1%, 0.1W, 0603; Manufacturer: Yageo America; CompType: Resistor; Res_ohm: 27000; Value_Code: 27k0; Tolerance_%: 1; Power_W: 0.1; VDC_V: 150; TempCo: 200 ppm/C; U/M: EA
R29 R31 R43 = CRCW0603100KFKEA: as R61 on sheet TIDA-00807_MICROCONTROLLER
R30 R32 R34 = ERJ-8ENF3323V: RES, 332k ohm, 1%, 0.25W, 1206; Manufacturer: Panasonic; CompType: Resistor; Res_ohm: 332000; Tolerance_%: 1; Power_W: 0.25; VDC_V: 200; TempCo: 100 ppm/C; EIA_Code: E96; U/M: EA
R33 R35 R37 R39 = RC0603FR-0747KL: as R1 on sheet TIDA-00807_MICROCONTROLLER
R40 = RNCF0603TKY10K0: RES, 10.0k ohm, 1%, 0.1W, 0603; Manufacturer: Stackpole Electronics Inc; CompType: Resistor; Res_ohm: 10000; Value_Code: 10k0; Tolerance_%: 0.01; Value1: 0.01%; Power_W: 0.063; Value2: 0.063W; VDC_V: 50; TempCo: 5 ppm/C; U/M: EA
R41 R42 = CRCW12062K80FKEA: RES, 2.80k ohm, 1%, 0.25W, 1206; Manufacturer: Vishay-Dale; CompType: Resistor; Res_ohm: 2800; Value_Code: 2k80; Tolerance_%: 1; Power_W: 0.25; VDC_V: 200; TempCo: 100 ppm/C; EIA_Code: E96; U/M: EA
R44 = RC0603FR-0730KL: as R6 on sheet TIDA-00807_MICROCONTROLLER
R46 = CRCW06031M00FKEA: RES, 1.00Meg ohm, 1%, 0.1W, 0603; Manufacturer: Vishay-Dale; CompType: Resistor; Res_ohm: 1000000; Value_Code: 1M00; Tolerance_%: 1; Power_W: 0.1; VDC_V: 75; TempCo: 100 ppm/C; EIA_Code: E96; U/M: EA
TP1-TP7 = TP_H0.45P0.75: Manufacturer: Texas Instruments; CompType: Pad
U2 = SN74LVC1G3157DBVR: IC, SWITCH, SPDT, SOT23-6; Manufacturer: TEXAS INSTRUMENTS; SymbolCreator: x0199378
U3 = DAC101C081CIMK: 10-Bit Micro Power Digital-to-Analog Converter with an I2C-Compatible Interface, 6-pin Tiny SOT23; Manufacturer: Texas Instruments; PackageTopMarking: X85C*XTT; PowerWise: N; CompType: D/A Converter
U4 = LMT87LPM: Analog Temperature Sensors with Class-AB Output, LP0003A; Manufacturer: Texas Instruments; SymbolCreator: Altium; CompType: IC; U/M: EA
U6 U8 = OPA2317IDR: Low-Offset, Rail-to-Rail I/O Operational Amplifier Precision Catalog, D0008A; Manufacturer: Texas Instruments; CompType: IC; U/M: EA
U7 = LM4041BIDBZ: IC, Micropower Shunt Voltage Reference 100 ppm/°C, 45µA-12mA,  Adjustable; Manufacturer: TI; Alternate Manufacturer: None; Area: 25500
U9 = LMV331IDBV: Single General Purpose Low-Voltage Comparator, DBV0005A; Manufacturer: Texas Instruments; SymbolCreator: a0411595; CompType: OpAmp IC

## Sheet TIDA-00807_POWER SUPPLY.SchDoc: POWER SUPPLY
size 431 x 279 mm; Date: Not shown in title block; ApprovedBy: Not shown in title block; CheckedBy: Not shown in title block; Author: Not shown in title block; CompanyName: Not shown in title block; DrawnBy: Srinivasa; Engineer: Srinivasa; Organization: Not shown in title block; Address1: Not shown in title block; Address2: Not shown in title block; Address3: Not shown in title block; Address4: Not shown in title block; DocumentNumber: 1; Revision: Use project parameter SCH_Rev; SheetNumber: 5; SheetTotal: 6; PageSetup: Record=PageOptions¦CenterHorizontal=True¦CenterVertical=True¦PrintScale=1.00¦XCorrection=1.00¦YCorrection=1.00¦PrintKind=0¦BorderSize=5000000¦LeftOffset=0¦BottomOffset=0¦Orientation=2¦PaperLength=1000¦PaperWidth=1000¦Scale=100¦PaperSource=15¦PrintQuality=600¦MediaType=1¦DitherType=10¦PaperKind=Letter¦PrintScaleMode=1
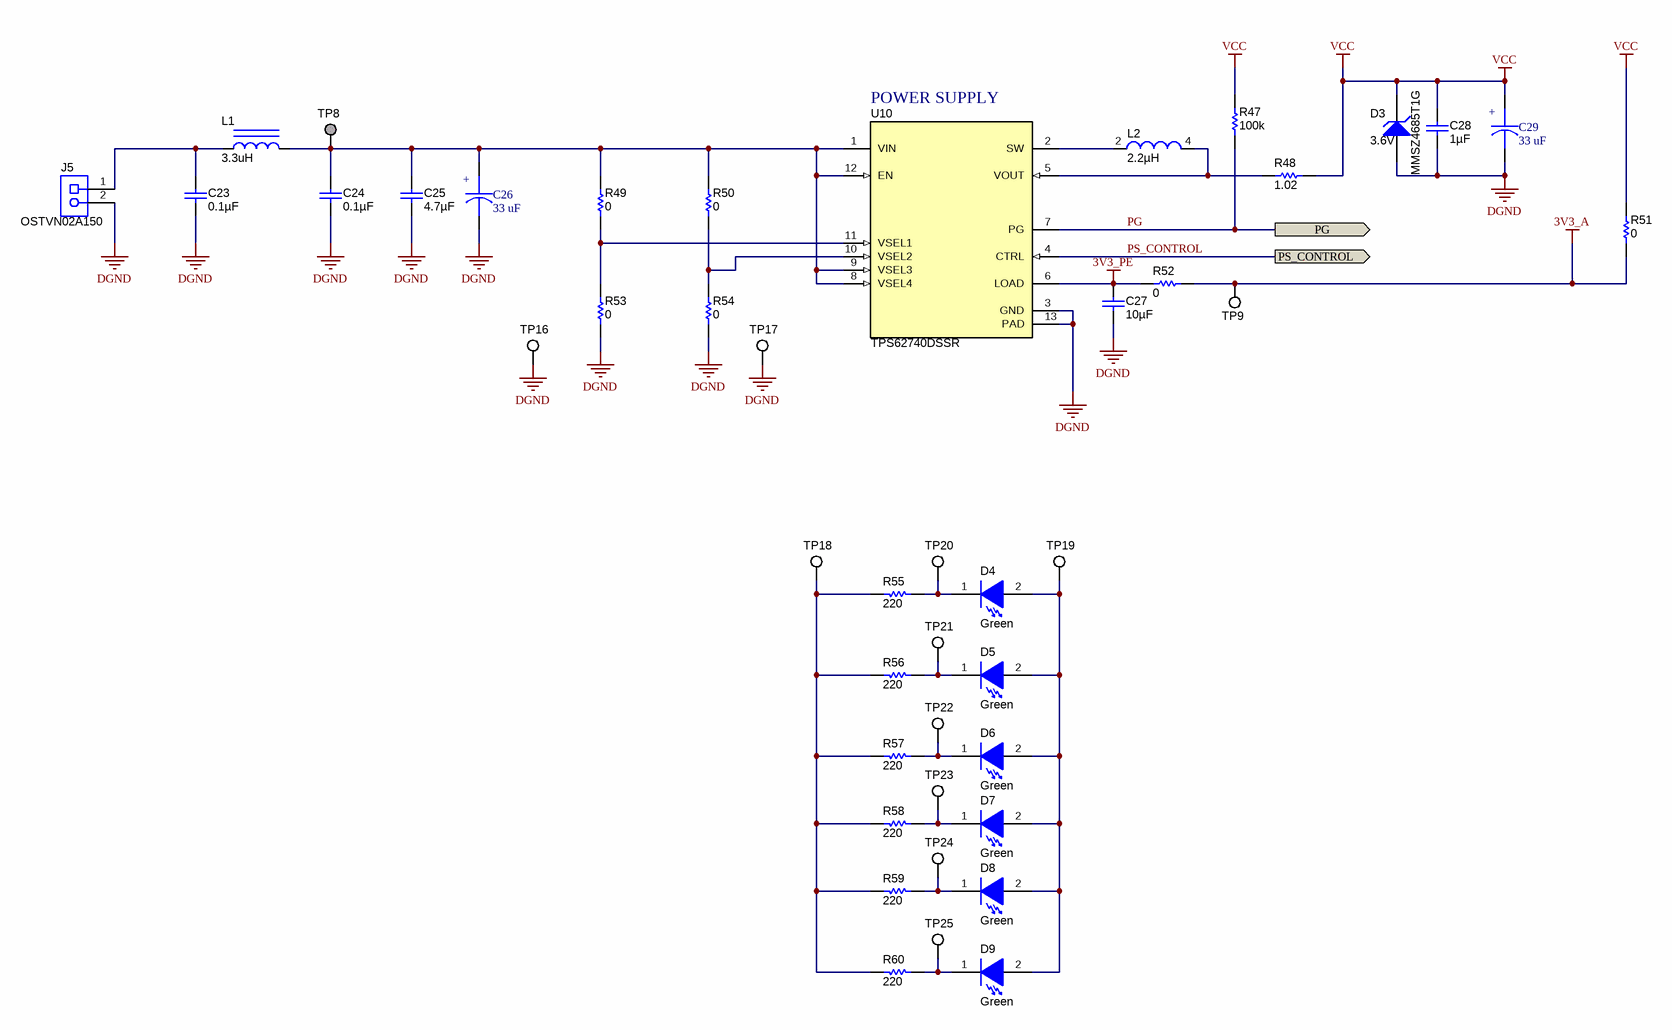
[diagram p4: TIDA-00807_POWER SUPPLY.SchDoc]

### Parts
C23  ValueDisplayed: 0.1µF  [0603]  (hidden comment: 06033C104JAT2A)
C24  ValueDisplayed: 0.1µF  [0603]  (hidden comment: 06033C104JAT2A)
C25  ValueDisplayed: 4.7µF  [0805_HV]  (hidden comment: C2012X5R1H475K125AB)
C26  value 33 uF  [CAP_POSCAP_D]  (hidden comment: T491D336M010AT)
C27  ValueDisplayed: 10µF  [1210]  (hidden comment: 1210YD106KAT2A)
C28  ValueDisplayed: 1µF  [0603]  (hidden comment: C0603C105K4PACTU)
C29  value 33 uF  [CAP_POSCAP_D]  (hidden comment: T491D336M010AT)
D3  MMSZ4685T1G  value 3.6V  [SOD-123]
D4  value Green  [WL-SMCW_GREEN]  (hidden comment: 150060GS75000)
D5  value Green  [WL-SMCW_GREEN]  (hidden comment: 150060GS75000)
D6  value Green  [WL-SMCW_GREEN]  (hidden comment: 150060GS75000)
D7  value Green  [WL-SMCW_GREEN]  (hidden comment: 150060GS75000)
D8  value Green  [WL-SMCW_GREEN]  (hidden comment: 150060GS75000)
D9  value Green  [WL-SMCW_GREEN]  (hidden comment: 150060GS75000)
J5  OSTVN02A150  [On-Shore_OSTVN02A150]
L1  value 3.3uH  [1210]  (hidden comment: B82422H1332K)
L2  ValueDisplayed: 2.2µH  [WE-TPC_3510]  (hidden comment: 744030002)
R47  value 100k  [0603]  (hidden comment: CRCW0603100KFKEA)
R48  value 1.02  [1206]  (hidden comment: RC1206FR-071R02L)
R49  ValueDisplayed: 0  [0603]  (hidden comment: ERJ-3GEY0R00V)
R50  ValueDisplayed: 0  [0603]  (hidden comment: ERJ-3GEY0R00V)
R51  ValueDisplayed: 0  [0603]  (hidden comment: ERJ-3GEY0R00V)
R52  value 0  [0805_HV]  (hidden comment: CRCW08050000Z0EA)
R53  ValueDisplayed: 0  [0603]  (hidden comment: ERJ-3GEY0R00V)
R54  ValueDisplayed: 0  [0603]  (hidden comment: ERJ-3GEY0R00V)
R55  value 220  [0603]  (hidden comment: CRCW0603220RJNEA)
R56  value 220  [0603]  (hidden comment: CRCW0603220RJNEA)
R57  value 220  [0603]  (hidden comment: CRCW0603220RJNEA)
R58  value 220  [0603]  (hidden comment: CRCW0603220RJNEA)
R59  value 220  [0603]  (hidden comment: CRCW0603220RJNEA)
R60  value 220  [0603]  (hidden comment: CRCW0603220RJNEA)
TP8  TESTPOINT  [TP_H045P075]  (value not drawn)  (no BOM)
TP9  TP105-01-09  [CC_TP105-01-09]  (value not drawn)
TP16  TP105-01-09  [CC_TP105-01-09]  (value not drawn)
TP17  TP105-01-09  [CC_TP105-01-09]  (value not drawn)
TP18  TP105-01-09  [CC_TP105-01-09]  (value not drawn)
TP19  TP105-01-09  [CC_TP105-01-09]  (value not drawn)
TP20  TP105-01-09  [CC_TP105-01-09]  (value not drawn)
TP21  TP105-01-09  [CC_TP105-01-09]  (value not drawn)
TP22  TP105-01-09  [CC_TP105-01-09]  (value not drawn)
TP23  TP105-01-09  [CC_TP105-01-09]  (value not drawn)
TP24  TP105-01-09  [CC_TP105-01-09]  (value not drawn)
TP25  TP105-01-09  [CC_TP105-01-09]  (value not drawn)
U10  TPS62740DSSR  [DSS0012A]

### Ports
PG (out), PS_CONTROL (out)

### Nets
3V3_A: R51.1 R52.2 TP9.1
3V3_PE: C27.1 R52.1 U10.6(LOAD)
DGND: C23.2 C24.2 C25.2 C26.2 C27.2 C28.2 C29.2 D3.2(A) J5.2 R53.1 R54.1 TP16.1 TP17.1 U10.3(GND) U10.13(PAD)
VCC: C28.1 C29.1 D3.1(K) R47.2 R48.2 R51.2
PG: R47.1 U10.7(PG) ; port PG
PS_CONTROL: U10.4(CTRL) ; port PS_CONTROL
NetC23_1: C23.1 J5.1 L1.1
NetC24_1: C24.1 C25.1 C26.1 L1.2 R49.2 R50.2 TP8.1 U10.1(VIN) U10.8(VSEL4) U10.9(VSEL3) U10.12(EN)
NetD4_1: D4.1(K) R55.2 TP20.1
NetD4_2: D4.2(A) D5.2(A) D6.2(A) D7.2(A) D8.2(A) D9.2(A) TP19.1
NetD5_1: D5.1(K) R56.2 TP21.1
NetD6_1: D6.1(K) R57.2 TP22.1
NetD7_1: D7.1(K) R58.2 TP23.1
NetD8_1: D8.1(K) R59.2 TP24.1
NetD9_1: D9.1(K) R60.2 TP25.1
NetL2_2: L2.2 U10.2(SW)
NetL2_4: L2.4 R48.1 U10.5(VOUT)
NetR49_1: R49.1 R53.2 U10.11(VSEL1)
NetR50_1: R50.1 R54.2 U10.10(VSEL2)
NetR55_1: R55.1 R56.1 R57.1 R58.1 R59.1 R60.1 TP18.1

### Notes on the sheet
- (near U10) POWER SUPPLY

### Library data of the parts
C23 C24 = 06033C104JAT2A: as C3 on sheet TIDA-00807_MICROCONTROLLER
C25 = C2012X5R1H475K125AB: 4.7µF ±10% 50V X5R Ceramic Capacitor; Manufacturer: TDK; Polarized: N; Value: 4.7uF; U/M: EA; Cap_F: 0.0000047; Tolerance_%: 10; Value1: Unknown; VDC_V: 50; TaMin_C: -55; TaMax_C: 85; Cap_Case: 0805
C26 C29 = CAP_TANT_47U_10V: CAP TANT 33UF 10V 20% 2917; Manufacturer: Kemet; Area: 62100
C27 = 1210YD106KAT2A: CAP, CERM, 10uF, 16V, +/-10%, X5R, 1210; Manufacturer: AVX; Polarized: N; CompType: Capacitor; U/M: EA; Cap_F: 0.00001; Tolerance_%: 10; Value1: Unknown; VDC_V: 16; TaMin_C: -55; TaMax_C: 85
C28 = C0603C105K4PACTU: CAP, CERM, 1uF, 16V, +/-10%, X5R, 0603; Manufacturer: Kemet; Polarized: N; CompType: Capacitor; U/M: EA; Cap_F: 0.000001; Tolerance_%: 10; Value1: Unknown; VDC_V: 16; TaMin_C: -55; TaMax_C: 85
D3 = MMSZ4685T1G: Diode, Zener, 3.6 V, 500 mW, SOD-123; Manufacturer: ON Semiconductor; SymbolCreator: a0412235; U/M: EA; Power_W: 0.5; Vz_V: 3.6; Value1: 0.5W; RJA_CperW: 340; AEC Category: Q101
D4-D9 = 150060GS75000: LED, Green, SMD; Manufacturer: Wurth Elektronik; Type: InGaN; Vf_V: 3.2; Value2: 3.2V; Io_A: 0.02; Tjmax_C: 85; Value1: W; Angle: 140; U/M: EA
J5 = OSTVN02A150: as J3 on sheet TIDA-00807_OP_AMP and REFERENCE
L1 = IND_B82422H1332K: Inductor, Chip, 3.3uH 770MA 1210 10%; Manufacturer: EPCOS Inc; Area: 28000
L2 = 744030002: Inductor, Shielded Drum Core, Metal Composite, 2.2 µH, 0.74 A, 0.14 ohm, SMD; Manufacturer: Wurth Elektronik; SymbolCreator: a0411947; Ind_H: 2.2E-6; Value: 2.2uH; Imax_A: 0.74; Irms: 0.74A @ 40C rise; Isat: 0.8A @ 35% inductance drop; DCR_ohm: 0.14; Value2: 0.74A; AEC Category: Q200
R47 = CRCW0603100KFKEA: as R61 on sheet TIDA-00807_MICROCONTROLLER
R48 = RC1206FR-071R02L: RES, 1.02 ohm, 1%, 0.25W, 1206; Manufacturer: Yageo America; CompType: Resistor; Value_Code: 1R02; Tolerance_%: 1; Power_W: 0.25; VDC_V: 200; TempCo: 200 ppm/C; EIA_Code: E96; U/M: EA
R49-R51 R53 R54 = ERJ-3GEY0R00V: as R45 on sheet TIDA-00807_MICROCONTROLLER
R52 = CRCW08050000Z0EA: RES, 0 ohm, 5%, 0.125W, 0805; Manufacturer: Vishay-Dale; CompType: Resistor; Value_Code: 0000; Tolerance_%: 5; Power_W: 0.125; VDC_V: 150; TempCo: 200 ppm/C; EIA_Code: E24; U/M: EA
R55-R60 = CRCW0603220RJNEA: RES, 220 ohm, 5%, 0.1W, 0603; Manufacturer: Vishay-Dale; CompType: Resistor; Value_Code: 220R; Tolerance_%: 5; Power_W: 0.1; VDC_V: 75; TempCo: 200 ppm/C; EIA_Code: E24; U/M: EA
TP8 = TP_H0.45P0.75: as TP1 on sheet TIDA-00807_OP_AMP and REFERENCE
TP9 TP16-TP25 = TP105-01-09: as TP10 on sheet TIDA-00807_MICROCONTROLLER
U10 = TPS62740DSSR: 360nA IQ Step Down Converter for Low Power Applications, DSS0012A; Alternate PartNumber: TPS62740DSST; Manufacturer: Texas Instruments; SymbolCreator: Altium; CompType: IC; U/M: EA

## Sheet TIDA-00807_EVM_Hardware.SchDoc
size 431 x 279 mm; Date: Not shown in title block; ApprovedBy: Not shown in title block; CheckedBy: Not shown in title block; Author: Not shown in title block; CompanyName: Not shown in title block; DrawnBy: Srinivasa; Engineer: Srinivasa; Organization: Not shown in title block; Address1: Not shown in title block; Address2: Not shown in title block; Address3: Not shown in title block; Address4: Not shown in title block; DocumentNumber: 1; Revision: Use project parameter SCH_Rev; SheetNumber: 6; SheetTotal: 6; PageSetup: Record=PageOptions¦CenterHorizontal=True¦CenterVertical=True¦PrintScale=1.00¦XCorrection=1.00¦YCorrection=1.00¦PrintKind=0¦BorderSize=5000000¦LeftOffset=0¦BottomOffset=0¦Orientation=2¦PaperLength=1000¦PaperWidth=1000¦Scale=100¦PaperSource=15¦PrintQuality=600¦MediaType=1¦DitherType=10¦PaperKind=Letter¦PrintScaleMode=1
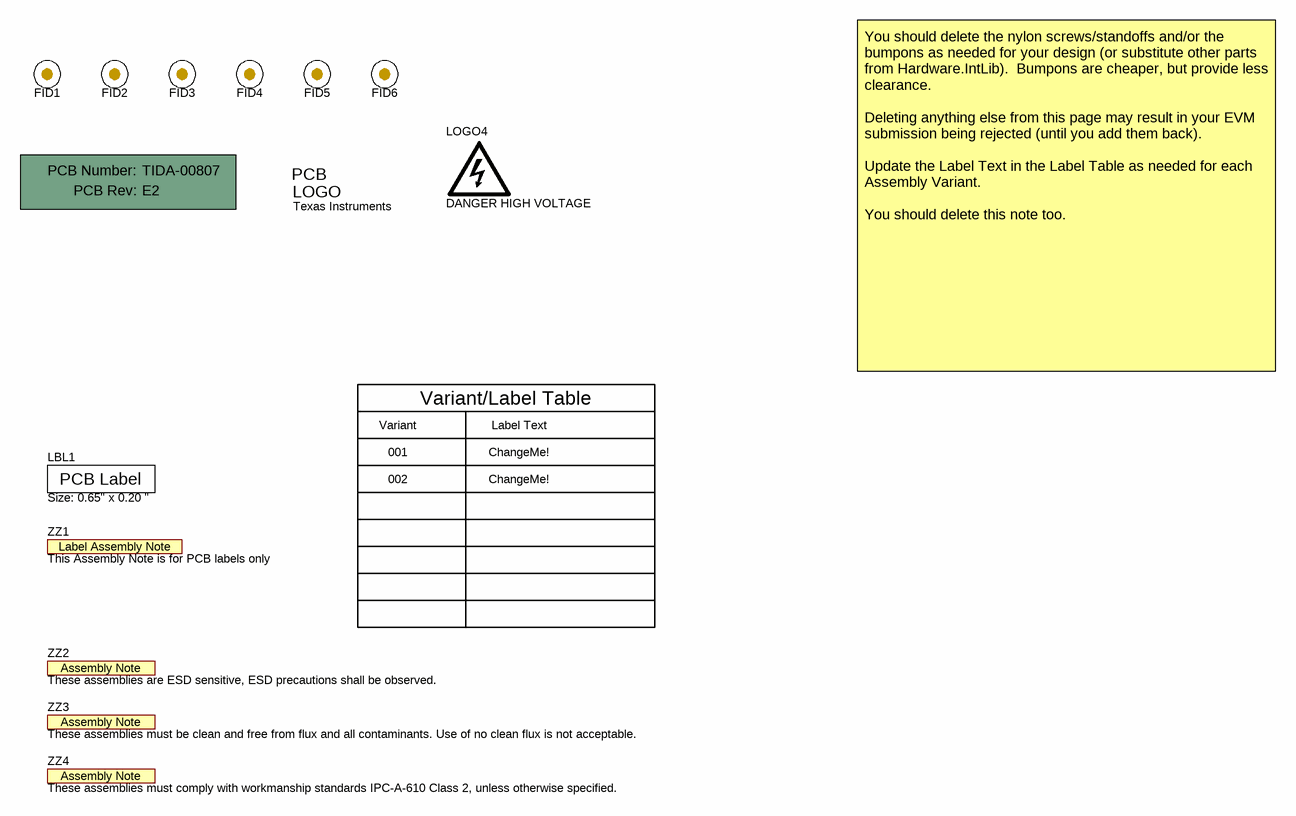
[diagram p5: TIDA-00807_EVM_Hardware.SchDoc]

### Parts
!PCB1  Printed Circuit Board  (value not drawn)  (mechanical)
FID1  Fiducial  [Fiducial10-20]  (value not drawn)
FID2  Fiducial  [Fiducial10-20]  (value not drawn)
FID3  Fiducial  [Fiducial10-20]  (value not drawn)
FID4  Fiducial  [Fiducial10-20]  (value not drawn)
FID5  Fiducial  [Fiducial10-20]  (value not drawn)
FID6  Fiducial  [Fiducial10-20]  (value not drawn)
LBL1  Size: 0.65" x 0.20 "  [Label_650x200]
Logo1  Texas Instruments  [TI_Stacked_Overlay_Small]  (no BOM)
LOGO4  DANGER HIGH VOLTAGE  [IEC_HighVoltage_medium]  (no BOM)
ZZ1  This Assembly Note is for PCB labels only  [AssemblyNoteLabel]  (no BOM)
ZZ2  These assemblies are ESD sensitive, ESD precautions shall be observed.  [AssemblyNote]  (no BOM)
ZZ3  These assemblies must be clean and free from flux and all contaminants. Use of no clean flux is not acceptable.  [AssemblyNote]  (no BOM)
ZZ4  These assemblies must comply with workmanship standards IPC-A-610 Class 2, unless otherwise specified.  [AssemblyNote]  (no BOM)

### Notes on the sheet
- Variant
- Variant/Label Table
- Label Text
- You should delete the nylon screws/standoffs and/or the bumpons as needed for your design (or substitute other parts from Hardware.IntLib).  Bumpons are cheaper, but provide less clearance.
  Deleting anything else from this page may result in your EVM submission being rejected (until you add them back).
  Update the Label Text in the Label Table as needed for each Assembly Variant.
  You should delete this note too.
- 001
- 002
- ChangeMe!

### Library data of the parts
!PCB1 = PCB: Manufacturer: Any; PartNumber: TIDA-00807; SymbolCreator: a0412235
FID1-FID6 = Fiducial: Fiducial mark.  There is nothing to buy or mount.; SymbolCreator: codlsc
LBL1 = THT-14-423-10: Thermal Transfer Printable Labels, 0.650" W x 0.200" H - 10,000 per roll; Manufacturer: Brady; SymbolCreator: a0412235; CompType: Label
Logo1 = TI_Logo: Texas Instrument Corporate Signature; SymbolCreator: codlsc
LOGO4 = IEC_HighVoltage: IEC 61010-1 High Voltage Warning; SymbolCreator: a0412235
ZZ1 = AssemblyNoteLabel: SymbolCreator: a0412235
ZZ2-ZZ4 = AssemblyNote: SymbolCreator: codlsc

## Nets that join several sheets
3V3_A: TIDA-00807_MICROCONTROLLER (5 pins), TIDA-00807_OP_AMP and REFERENCE (12 pins), TIDA-00807_POWER SUPPLY (R51.1 R52.2 TP9.1)
DGND: TIDA-00807_MICROCONTROLLER (C10.2 FB2.2 J2.4 U5.3), TIDA-00807_OP_AMP and REFERENCE (24 pins), TIDA-00807_POWER SUPPLY (15 pins)
VCC: TIDA-00807_MICROCONTROLLER (J1.1 JP2.1 R2.2 R69.2), TIDA-00807_OP_AMP and REFERENCE (6 pins), TIDA-00807_POWER SUPPLY (6 pins)
CUR_H: TIDA-00807_MICROCONTROLLER (R64.2), TIDA-00807_OP_AMP and REFERENCE (C18.2 R27.2 TP6.1)
CUR_L: TIDA-00807_MICROCONTROLLER (R65.2), TIDA-00807_OP_AMP and REFERENCE (C14.2 R17.2 TP3.1)
FAULT: TIDA-00807_MICROCONTROLLER (U1.5), TIDA-00807_OP_AMP and REFERENCE (R37.1 R46.2 U9.4)
I2C_SCL: TIDA-00807_MICROCONTROLLER (J2.2 U1.23), TIDA-00807_OP_AMP and REFERENCE (R8.1)
I2C_SDA: TIDA-00807_MICROCONTROLLER (J2.3 U1.22), TIDA-00807_OP_AMP and REFERENCE (R10.1)
PS_CONTROL: TIDA-00807_MICROCONTROLLER (R61.1 R66.2 R69.1), TIDA-00807_POWER SUPPLY (U10.4)
TEMP: TIDA-00807_MICROCONTROLLER (R45.2), TIDA-00807_OP_AMP and REFERENCE (C9.2 R9.2)
TEST_SEL: TIDA-00807_MICROCONTROLLER (R1.1 U1.14), TIDA-00807_OP_AMP and REFERENCE (U2.6)
V1: TIDA-00807_MICROCONTROLLER (R63.2), TIDA-00807_OP_AMP and REFERENCE (C22.2 R38.2 TP7.1)

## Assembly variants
001: not fitted FID1 FID2 FID3 FID4 FID5 FID6 R51 R53 R54 R62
